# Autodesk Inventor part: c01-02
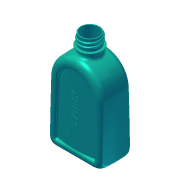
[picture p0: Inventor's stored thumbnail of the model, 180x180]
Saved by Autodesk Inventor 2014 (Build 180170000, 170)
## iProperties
Created: 2010-12
Part Number: c01-02
Material: Generic
Document SubType Name: Modeling
Designer: Thom Tremblay
Density: 1 g/cm^3
Appearance: Turquoise
Author: Thom Tremblay
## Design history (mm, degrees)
sketch "Sketch1"
  geometry: L1 (-25, 0)-(25, 0); L2 (25, 0)-(25, 80); L3 (25, 80)-(-25, 80); L4 (-25, 80)-(-25, 0); 2 further points
  constraints: 8 end point, 2 parallel, 1 coincident, 1 horizontal, 1 midpoint, 1 perpendicular
  dimensions: "d0" = 50 distance of L3.end L2.end; "d1" = 80 distance of L2.end L1.end
extrude "Extrusion1" new body sketch "Sketch1" distance "d2" = 15; taper "d3" = 0 deg
feature "FaceDraft1" dims angle "d4" = -2 deg
fillet "Fillet1"
fillet "Fillet2" dims "d5" = 8, "d6" = 8, "d7" = 8, "d8" = 8, "d9" = 8, "d10" = 8, "d11" = 3, "d12" = 3, "d13" = 3, "d14" = 6, "d15" = 5
sketch "Sketch2"
  geometry: L1 (5.522, 12)-(38.474, 12) reference; L2 (0, 0)-(43.996, 0) reference; L3 (41.757, 6.83)-(41.995, 0); L4 (41.925, 2)-(2.071, 2); L5 (2.001, 0)-(2.24, 6.83); L6 (5.522, 10)-(38.474, 10); A1 r 5.284 centre (38.474, 6.716) between (43.755, 6.9) and (38.474, 12) reference; A2 r 5.284 centre (5.522, 6.716) between (5.522, 12) and (0.241, 6.9) reference; A3 r 3.284 centre (38.474, 6.716) between (41.757, 6.83) and (38.474, 10); A4 r 3.284 centre (5.522, 6.716) between (5.522, 10) and (2.24, 6.83); 1 further point
  constraints: 8 end point, 4 point on circle, 4 point on line, 2 centre point, 1 other
  dimensions: "d16" = 2 radial gap between concentric circles of A2 A4
extrude "Extrusion2" cut sketch "Sketch2" distance "d17" = 1; taper "d18" = 0 deg
feature "FaceDraft2" dims angle "d19" = 15 deg
sketch "Sketch3" dims "d20" = 2.5
  geometry: L1 (16.476, 3)-(-16.476, 3) reference; L2 (16.476, 5.5)-(-16.476, 5.5); 9 further points
  constraints: 2 end point, 2 parallel, 1 horizontal alignment, 19 other
extrude "Extrusion3" cut sketch "Sketch3" distance "d21" = 3; taper "d22" = 0 deg
feature "FaceDraft3" dims angle "d23" = 10 deg
workplane "Work Plane1"
sketch "Sketch4"
  geometry: L1 (41.1, -1.222)-(41.476, -12) reference; L2 (41.476, -12)-(-8.524, -12) reference; L3 (-8.524, -12)-(-8.147, -1.222) reference; L4 (-3.776, 3)-(-1.272, 3) reference; L5 (-0.743, 0)-(33.695, 0) reference; L6 (34.225, 3)-(36.728, 3) reference; L7 (-11.024, -1.856)-(43.976, -1.856); A1 r 100 centre (16.476, -98) between (43.976, -1.856) and (-11.024, -1.856); 2 further points
  constraints: 2 end point, 2 point on circle, 1 centre point, 1 midpoint, 1 parallel, 1 vertical alignment, 4 other
  dimensions: "d25" = 100 radius of A1; "d26" = 14 distance edge to line of A1 L2; "d27" = 55 distance of L7.start L7.end
extrude_surface "ExtrusionSrf1" sketch "Sketch4" dims "d28" = 86, "d29" = 0
feature "Replace Face1"
fillet "Fillet3" dims "d34" = 1, "d35" = 2
mirror "Mirror1"
fillet "Fillet4" dims "d36" = 20
workplane "Work Plane3"
sketch "Sketch6"
  geometry: C1 r 9 at (0, 0); 1 further point
  constraints: 1 centre point, 1 coincident
  dimensions: "d38" = 18 diameter of C1
extrude "Top Boss" join sketch "Sketch6" distance "d39" = 16; taper "d40" = 0 deg
fillet "Fillet5" dims "d41" = 3
shell "Shell1" dims "d62" = 1
sketch "Sketch7"
  geometry: L1 (-9, 80.285)-(-9, 96) reference; C1 r 1 at (-9, 94.5); 1 further point
  constraints: 1 centre point, 1 point on line
  dimensions: "d42" = 1.5 distance of L1.end C1.centre; "d43" = 2 diameter of C1
coil "Coil2" sketch "Sketch7" pitch "d52" = 10; turns "d54" = 2; dims "d53" = 7, "d55" = 0, angle "d56" = 90 deg, angle "d57" = 90 deg, "d58" = 0, "d59" = 0
fillet "Fillet6" dims "d60" = 0.9
fillet "Fillet7" dims "d61" = 0.2
sketch "Sketch8"
  geometry: L1 (-9.664, 85.5)-(-11.164, 85.5); L2 (-11.164, 85.5)-(-11.164, 84.5); L3 (-11.164, 84.5)-(-9.664, 83.954); L4 (-9.664, 83.954)-(-9.664, 85.5); L5 (0.836, 2.555)-(0.836, 98.256); L6 (-9, 96)-(9, 96) reference; L7 (0, -19.758)-(0, 117.925) reference; 1 further point
  constraints: 10 end point, 2 parallel, 1 horizontal, 1 perpendicular
  dimensions: "d63" = 1 distance of L1.end L2.end; "d64" = 20 deg angle of L1 L3; "d65" = 10.5 distance between parallel lines of L6 L1; "d66" = 24 diameter of L2 L5; "d67" = 1.5 distance of L1.start L1.end
fillet "Fillet8"
revolve "Revolution1" stored, may be unused: angle "d69" = 90 deg
fillet "Fillet9" dims "d70" = 0.2, "d80" = 1
sketch "Sketch9"
  geometry: L1 (-3.447, 12.995)-(-3.447, 63.11); L2 (-3.447, 63.11)-(4.192, 63.11); L3 (4.192, 63.11)-(4.192, 12.995); L4 (4.192, 12.995)-(-3.447, 12.995); 1 further point
  constraints: 2 other
emboss "Emboss1" sketch "Sketch9" dims "d0" = 50, "d1" = 80, "d71" = 0.3, "d72" = 0
pattern_circular "Circular Pattern1" dims angle "d76" = 180 deg
feature "Rule Fillet1" dims "d73" = 0.05, "d74" = 0.05
body "Solid1"
body "Srf1"
node "Project Cut Edges1"
other parameters: "d79" = 90 deg
